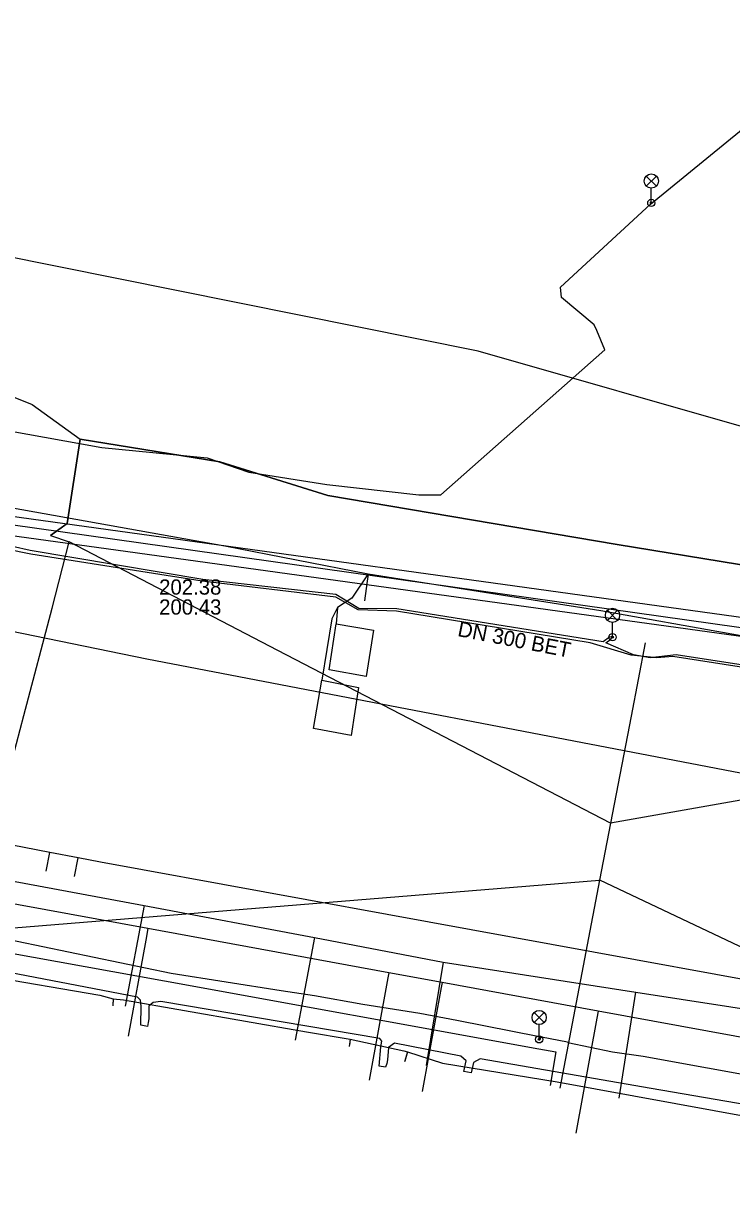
# Model space of a CAD drawing. Extents: x -596228 to -595156, y -1161235 to -1159373.
# Drawn here: x -595878.3 to -595841.1, y -1160347.3 to -1160286.1 of the extents above; entities that cross this region are included whole.
import ezdxf

# ---------------------------------------------------------------- set-up
doc = ezdxf.new("R2010")
doc.units = 0
for name, color, linetype in [('Vrstva 1', 7, 'Continuous'), ('Vrstva 10', 7, 'Continuous'), ('Vrstva 12', 7, 'Continuous'), ('Vrstva 14', 7, 'Continuous'), ('Vrstva 16', 7, 'Continuous'), ('Vrstva 33', 7, 'Continuous'), ('Vrstva 4', 7, 'Continuous'), ('Vrstva 42', 7, 'Continuous'), ('Vrstva 54', 7, 'Continuous'), ('Vrstva 55', 7, 'Continuous'), ('Vrstva 58', 7, 'Continuous'), ('Vrstva 9', 7, 'Continuous')]:
    doc.layers.add(name, color=color, linetype=linetype)

msp = doc.modelspace()

# ---------------------------------------------------------------- linework, layer by layer
at = {"layer": 'Vrstva 1'}
for p, q in [((-595854.43, -1160303.29), (-595897.18, -1160294.69)), ((-595806.58, -1160316.98), (-595854.43, -1160303.29)), ((-595871.84, -1160319.47), (-595888.65, -1160316.04)), ((-595871.843, -1160319.471), (-595888.65, -1160316.042)), ((-595832.393, -1160327.051), (-595871.84, -1160319.47)), ((-595832.39, -1160327.05), (-595871.84, -1160319.47))]:
    msp.add_line(p, q, dxfattribs=at)
at = {"layer": 'Vrstva 10'}
for p, q in [((-595887.89, -1160310.72), (-595811.15, -1160321.35)), ((-595887.89, -1160310.72), (-595811.15, -1160321.35)), ((-595888.05, -1160311.71), (-595811.33, -1160322.33)), ((-595888.05, -1160311.71), (-595811.33, -1160322.33))]:
    msp.add_line(p, q, dxfattribs=at)
at = {"layer": 'Vrstva 12'}
for p, q in [((-595873.61, -1160337.32), (-595873.63, -1160337.69)), ((-595863.45, -1160339.05), (-595861.16, -1160339.45)), ((-595861.16, -1160339.45), (-595861.21, -1160339.83)), ((-595858.15, -1160340.11), (-595858.3, -1160340.64))]:
    msp.add_line(p, q, dxfattribs=at)
for points in [[(-595930.09, -1160299.24), (-595889.94, -1160310.85), (-595809.314, -1160322.217)], [(-595909.31, -1160329.42), (-595887.62, -1160333.37), (-595870.92, -1160336.38), (-595851.25, -1160339.95)], [(-595890.71, -1160334.18), (-595888.67, -1160334.6), (-595880.28, -1160336.12), (-595874.32, -1160337.13), (-595873.61, -1160337.32)], [(-595873.61, -1160337.32), (-595873.07, -1160337.37), (-595863.45, -1160339.05)], [(-595861.16, -1160339.45), (-595858.34, -1160340.05), (-595858.15, -1160340.11)], [(-595851.25, -1160339.95), (-595850.36, -1160340.1), (-595850.65, -1160341.87)], [(-595858.15, -1160340.11), (-595856.31, -1160340.7), (-595850.28, -1160341.68), (-595840.02, -1160343.56)]]:
    msp.add_lwpolyline(points, dxfattribs=at)
at = {"layer": 'Vrstva 14'}
for points in [[(-595796.62, -1160347.3), (-595824.314, -1160342.334), (-595828.542, -1160341.559), (-595835.203, -1160340.338), (-595848.129, -1160337.968), (-595856.324, -1160336.466), (-595859.13, -1160335.952), (-595871.786, -1160333.632), (-595881.289, -1160331.89), (-595903.564, -1160327.806)], [(-595871.786, -1160333.632), (-595871.898, -1160334.244), (-595872.821, -1160339.286)], [(-595859.13, -1160335.952), (-595859.179, -1160336.215), (-595860.165, -1160341.598)], [(-595856.324, -1160336.466), (-595856.371, -1160336.72), (-595857.375, -1160342.199)], [(-595848.129, -1160337.968), (-595848.197, -1160338.334), (-595849.304, -1160344.376)]]:
    msp.add_lwpolyline(points, dxfattribs=at)
at = {"layer": 'Vrstva 16'}
for p, q in [((-595871.98, -1160332.41), (-595872.98, -1160337.71)), ((-595863.04, -1160334.1), (-595864.06, -1160339.5)), ((-595856.28, -1160335.39), (-595857.16, -1160340.82)), ((-595847.03, -1160342.55), (-595846.15, -1160336.98))]:
    msp.add_line(p, q, dxfattribs=at)
msp.add_lwpolyline([(-595917.38, -1160324.14), (-595910, -1160325.618), (-595909.091, -1160325.778), (-595892.958, -1160328.622), (-595889.882, -1160329.258), (-595889.508, -1160329.332), (-595889.042, -1160329.399), (-595888.212, -1160329.541), (-595887.856, -1160329.621), (-595887.183, -1160329.739), (-595886.59, -1160329.7), (-595871.98, -1160332.41), (-595863.04, -1160334.1), (-595856.28, -1160335.39), (-595846.15, -1160336.98), (-595838.77, -1160338.11)], dxfattribs=at)
at = {"layer": 'Vrstva 33'}
for p, q in [((-595845.601, -1160294.085), (-595845.071, -1160294.615)), ((-595845.601, -1160294.615), (-595845.071, -1160294.085)), ((-595845.336, -1160295.5), (-595845.336, -1160294.725)), ((-595847.641, -1160316.905), (-595847.111, -1160317.435)), ((-595847.641, -1160317.435), (-595847.111, -1160316.905)), ((-595847.376, -1160318.32), (-595847.376, -1160317.545)), ((-595851.495, -1160338.038), (-595850.965, -1160338.568)), ((-595851.495, -1160338.568), (-595850.965, -1160338.038)), ((-595851.23, -1160339.453), (-595851.23, -1160338.678))]:
    msp.add_line(p, q, dxfattribs=at)
for centre, radius in [((-595845.336, -1160294.35), 0.375), ((-595845.336, -1160295.5), 0.19), ((-595845.336, -1160295.5), 0.05), ((-595847.376, -1160317.17), 0.375), ((-595847.376, -1160318.32), 0.19), ((-595847.376, -1160318.32), 0.05), ((-595851.23, -1160338.303), 0.375), ((-595851.23, -1160339.453), 0.19), ((-595851.23, -1160339.453), 0.05)]:
    msp.add_circle(centre, radius, dxfattribs=at)
at = {"layer": 'Vrstva 42'}
for p, q in [((-595876.906, -1160312.977), (-595875.92, -1160313.31)), ((-595876.906, -1160312.977), (-595875.92, -1160313.31)), ((-595876.906, -1160312.977), (-595875.92, -1160313.31)), ((-595860.217, -1160314.981), (-595860.415, -1160316.41))]:
    msp.add_line(p, q, dxfattribs=at)
for points in [[(-595943.26, -1160323.541), (-595943.78, -1160322.58), (-595940.91, -1160302.02), (-595939.31, -1160301.1), (-595930.15, -1160301.19), (-595925.58, -1160301.75), (-595922.51, -1160298.12), (-595919.61, -1160297.13), (-595916.66, -1160297.13), (-595905.75, -1160297.26), (-595900.08, -1160297.55), (-595895.98, -1160298.37), (-595889.04, -1160301.63), (-595877.87, -1160306.09), (-595875.35, -1160307.92), (-595868.01, -1160309.1), (-595862.33, -1160310.88), (-595847.13, -1160313.44), (-595833.42, -1160315.69)], [(-595943.26, -1160323.541), (-595943.78, -1160322.58), (-595940.91, -1160302.02), (-595939.31, -1160301.1), (-595930.15, -1160301.19), (-595925.58, -1160301.75), (-595922.51, -1160298.12), (-595919.61, -1160297.13), (-595916.66, -1160297.13), (-595905.75, -1160297.26), (-595900.08, -1160297.55), (-595895.98, -1160298.37), (-595889.04, -1160301.63), (-595877.87, -1160306.09), (-595875.35, -1160307.92), (-595868.01, -1160309.1), (-595862.33, -1160310.88), (-595847.13, -1160313.44), (-595833.42, -1160315.69)], [(-595943.26, -1160323.541), (-595943.78, -1160322.58), (-595940.91, -1160302.02), (-595939.31, -1160301.1), (-595930.15, -1160301.19), (-595925.58, -1160301.75), (-595922.51, -1160298.12), (-595919.61, -1160297.13), (-595916.66, -1160297.13), (-595905.75, -1160297.26), (-595900.08, -1160297.55), (-595895.98, -1160298.37), (-595889.04, -1160301.63), (-595877.87, -1160306.09), (-595875.35, -1160307.92), (-595868.01, -1160309.1), (-595862.33, -1160310.88), (-595847.13, -1160313.44), (-595833.42, -1160315.69)], [(-595943.26, -1160323.541), (-595943.78, -1160322.58), (-595940.91, -1160302.02), (-595939.31, -1160301.1), (-595930.15, -1160301.19), (-595925.58, -1160301.75), (-595922.51, -1160298.12), (-595919.61, -1160297.13), (-595916.66, -1160297.13), (-595905.75, -1160297.26), (-595900.08, -1160297.55), (-595895.98, -1160298.37), (-595889.04, -1160301.63), (-595877.87, -1160306.09), (-595875.35, -1160307.92), (-595868.01, -1160309.1), (-595862.33, -1160310.88), (-595847.13, -1160313.44), (-595833.42, -1160315.69)], [(-595943.78, -1160322.58), (-595940.91, -1160302.02), (-595939.31, -1160301.1), (-595930.15, -1160301.19), (-595925.58, -1160301.75), (-595922.51, -1160298.12), (-595919.61, -1160297.13), (-595916.66, -1160297.13), (-595905.75, -1160297.26), (-595900.08, -1160297.55), (-595895.98, -1160298.37), (-595889.04, -1160301.63), (-595877.87, -1160306.09), (-595875.35, -1160307.92), (-595876.03, -1160312.35), (-595876.906, -1160312.977)], [(-595943.78, -1160322.58), (-595940.91, -1160302.02), (-595939.31, -1160301.1), (-595930.15, -1160301.19), (-595925.58, -1160301.75), (-595922.51, -1160298.12), (-595919.61, -1160297.13), (-595916.66, -1160297.13), (-595905.75, -1160297.26), (-595900.08, -1160297.55), (-595895.98, -1160298.37), (-595889.04, -1160301.63), (-595877.87, -1160306.09), (-595875.35, -1160307.92), (-595876.03, -1160312.35), (-595876.906, -1160312.977)], [(-595895.894, -1160304.949), (-595895.931, -1160305.565), (-595896.41, -1160308.706), (-595893.65, -1160309.078), (-595880.587, -1160311.231), (-595867.748, -1160313.527), (-595860.217, -1160314.981), (-595847.991, -1160316.922), (-595834.216, -1160319.371), (-595820.364, -1160321.5), (-595806.264, -1160323.708), (-595792.142, -1160326.114), (-595783.529, -1160327.233), (-595777.032, -1160326.773), (-595764.779, -1160324.315), (-595754.282, -1160321.569), (-595753.606, -1160323.921), (-595750.637, -1160332.868), (-595750.632, -1160333.38), (-595740.462, -1160333.548), (-595739.673, -1160332.748), (-595739.749, -1160331.939)], [(-595876.906, -1160312.977), (-595876.03, -1160312.35), (-595875.35, -1160307.92), (-595868.01, -1160309.1), (-595862.33, -1160310.88), (-595847.13, -1160313.44), (-595833.42, -1160315.69)], [(-595876.906, -1160312.977), (-595876.03, -1160312.35), (-595875.35, -1160307.92), (-595868.01, -1160309.1), (-595862.33, -1160310.88), (-595847.13, -1160313.44), (-595833.42, -1160315.69)], [(-595875.35, -1160307.92), (-595876.03, -1160312.35), (-595876.906, -1160312.977)], [(-595833.42, -1160315.69), (-595847.13, -1160313.44), (-595862.33, -1160310.88), (-595868.01, -1160309.1), (-595875.35, -1160307.92), (-595876.03, -1160312.35), (-595876.906, -1160312.977)], [(-595896.41, -1160308.706), (-595893.65, -1160309.078), (-595880.587, -1160311.231), (-595867.748, -1160313.527), (-595860.217, -1160314.981), (-595861.066, -1160316.276), (-595861.82, -1160316.751)], [(-595861.82, -1160316.751), (-595862.125, -1160317.355), (-595862.65, -1160320.581), (-595860.72, -1160320.968), (-595861.116, -1160323.493), (-595863.085, -1160323.124), (-595862.65, -1160320.581)], [(-595861.82, -1160316.751), (-595861.897, -1160317.622), (-595859.94, -1160317.944), (-595860.317, -1160320.384), (-595862.273, -1160320.042), (-595861.897, -1160317.622)], [(-595836.883, -1160343.496), (-595845.341, -1160342.033), (-595854.333, -1160340.484), (-595854.676, -1160340.664), (-595854.797, -1160341.206), (-595854.987, -1160341.169), (-595855.185, -1160341.133), (-595855.061, -1160340.573), (-595855.35, -1160340.333), (-595858.832, -1160339.656), (-595859.145, -1160339.886), (-595859.2, -1160340.524), (-595859.233, -1160340.721), (-595859.299, -1160340.909), (-595859.642, -1160340.858), (-595859.543, -1160339.847), (-595859.5, -1160339.546), (-595859.608, -1160339.411), (-595871.11, -1160337.455), (-595871.508, -1160337.519), (-595871.749, -1160337.716), (-595871.743, -1160338.377), (-595871.778, -1160338.575), (-595871.807, -1160338.774), (-595872.168, -1160338.699), (-595872.148, -1160337.707), (-595872.173, -1160337.392), (-595872.34, -1160337.244), (-595880.463, -1160335.669)]]:
    msp.add_lwpolyline(points, dxfattribs=at)
at = {"layer": 'Vrstva 54'}
for p, q in [((-595876.83, -1160316.8), (-595875.92, -1160313.31)), ((-595864.96, -1160319.01), (-595875.92, -1160313.31)), ((-595878.31, -1160322.44), (-595876.83, -1160316.8)), ((-595847.48, -1160328.1), (-595864.96, -1160319.01)), ((-595845.66, -1160318.62), (-595846.4, -1160322.47)), ((-595879.08, -1160325.37), (-595878.31, -1160322.44)), ((-595846.4, -1160322.47), (-595847.48, -1160328.1)), ((-595829.53, -1160324.9), (-595847.48, -1160328.1)), ((-595847.48, -1160328.1), (-595848.05, -1160331.08)), ((-595881.29, -1160333.8), (-595848.05, -1160331.08)), ((-595848.05, -1160331.08), (-595850.15, -1160342.01)), ((-595848.05, -1160331.08), (-595848.051, -1160331.075)), ((-595848.051, -1160331.075), (-595817.27, -1160345.66))]:
    msp.add_line(p, q, dxfattribs=at)
at = {"layer": 'Vrstva 55'}
for points in [[(-595901.76, -1160303.617), (-595899.3, -1160303.61), (-595896.29, -1160303.96), (-595886.03, -1160306.33), (-595879.17, -1160307.45), (-595874.21, -1160308.35), (-595868.67, -1160308.9), (-595866.48, -1160309.64), (-595862.38, -1160310.3), (-595857.55, -1160310.83), (-595856.39, -1160310.83), (-595847.78, -1160303.22), (-595848.19, -1160302.21), (-595848.33, -1160301.9), (-595850.06, -1160300.47), (-595850.11, -1160299.93), (-595845.38, -1160295.57), (-595833.73, -1160286.06)], [(-595835.05, -1160320.63), (-595844.03, -1160319.24), (-595845.4, -1160319.41), (-595846.27, -1160319.25), (-595847.717, -1160318.608), (-595847.467, -1160318.42), (-595847.38, -1160318.28), (-595847.539, -1160318.324), (-595847.862, -1160318.567), (-595858.71, -1160316.83), (-595860.7, -1160316.81), (-595861.92, -1160316.08), (-595868.9, -1160315.28), (-595877.97, -1160313.77), (-595878.908, -1160313.55)], [(-595880.03, -1160334.02), (-595870.57, -1160335.97), (-595864.78, -1160336.88), (-595863.031, -1160337.155), (-595860.49, -1160337.6), (-595857.5, -1160338.07), (-595855.56, -1160338.44), (-595851.22, -1160339.298), (-595851.21, -1160339.48), (-595851.102, -1160339.321), (-595849.74, -1160339.59), (-595849.72, -1160339.61), (-595847.37, -1160340.1), (-595845.76, -1160340.33), (-595839, -1160341.56)]]:
    msp.add_lwpolyline(points, dxfattribs=at)
at = {"layer": 'Vrstva 58'}
for p, q in [((-595873.61, -1160337.32), (-595873.63, -1160337.64)), ((-595861.16, -1160339.45), (-595861.2, -1160339.75)), ((-595858.15, -1160340.11), (-595858.29, -1160340.6))]:
    msp.add_line(p, q, dxfattribs=at)
for points in [[(-595835.09, -1160320.76), (-595844.21, -1160319.34), (-595845.05, -1160319.4), (-595846.39, -1160319.27), (-595848.55, -1160318.61), (-595858.73, -1160316.96), (-595860.74, -1160316.88), (-595861.92, -1160316.22), (-595868.93, -1160315.38), (-595877.95, -1160313.96), (-595881.67, -1160313.21)], [(-595890.71, -1160334.18), (-595888.67, -1160334.6), (-595880.28, -1160336.12), (-595874.32, -1160337.13), (-595873.61, -1160337.32)], [(-595873.61, -1160337.32), (-595873.07, -1160337.37), (-595863.45, -1160339.05), (-595861.16, -1160339.45)], [(-595861.16, -1160339.45), (-595858.34, -1160340.05), (-595858.15, -1160340.11)], [(-595858.15, -1160340.11), (-595856.31, -1160340.7), (-595850.28, -1160341.68), (-595840.02, -1160343.56)]]:
    msp.add_lwpolyline(points, dxfattribs=at)
at = {"layer": 'Vrstva 9'}
for p, q in [((-595877.14, -1160330.607), (-595876.951, -1160329.625)), ((-595875.648, -1160330.895), (-595875.458, -1160329.913)), ((-595875.648, -1160330.895), (-595875.458, -1160329.913)), ((-595834.84, -1160337.35), (-595874.28, -1160330.14))]:
    msp.add_line(p, q, dxfattribs=at)
msp.add_lwpolyline([(-595874.28, -1160330.14), (-595875.458, -1160329.913), (-595876.951, -1160329.625), (-595884.246, -1160328.217), (-595889.313, -1160327.239), (-595892.47, -1160326.63)], dxfattribs=at)

# ---------------------------------------------------------------- texts
at = {"layer": 'Vrstva 4'}
for s, p in [('202.38', (-595871.2, -1160316.083)), ('200.43', (-595871.2, -1160317.133))]:
    msp.add_text(s, height=0.8, dxfattribs=at).set_placement(p)
msp.add_text('DN 300 BET', height=0.8, rotation=349, dxfattribs=at).set_placement((-595855.555, -1160318.254))

doc.saveas('drawing.dxf')
